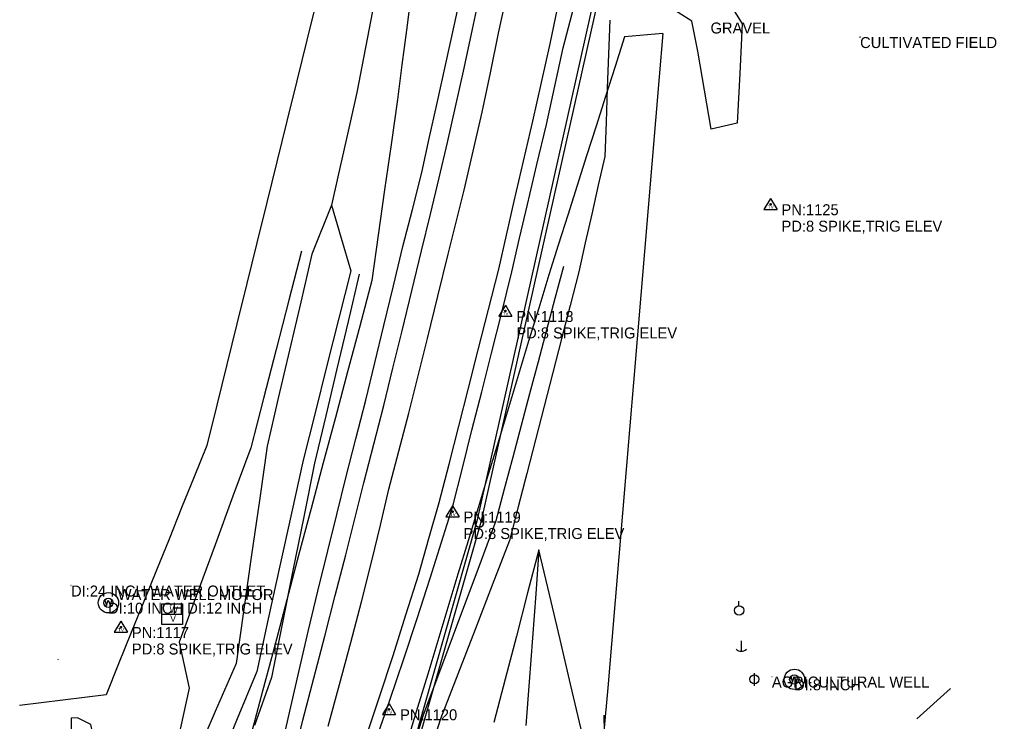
# Model space of a CAD drawing. Extents: x 1445297 to 1476720, y 2042269 to 2057889.
# Drawn here: x 1446111.2 to 1446556, y 2056093.5 to 2056413 of the extents above; entities that cross this region are included whole.
import ezdxf

# ---------------------------------------------------------------- set-up
doc = ezdxf.new("R2010")
doc.units = 0
for name, color, linetype in [('S_DITCHLINE', 7, 'Continuous'), ('S_DRG_PT_SYM', 7, 'Continuous'), ('S_DRIVEWAY', 7, 'Continuous'), ('S_EDGE_PAVEMENT', 7, 'Continuous'), ('S_FIBER_OPTIC_CABLE', 7, 'Continuous'), ('S_MISC_STRUCTURES_ANNOT', 7, 'Continuous'), ('S_MSC_PT_SYM', 7, 'Continuous'), ('S_PAVEMENT_CROWN', 7, 'Continuous'), ('S_SECONDARY_CTL', 7, 'Continuous'), ('S_SECONDARY_CTL_ANNOT', 7, 'Continuous'), ('S_SHOULDER', 7, 'Continuous'), ('S_STREAM', 7, 'Continuous'), ('S_SURVEY_TEXT_ANNOT', 7, 'Continuous'), ('S_TREE', 7, 'Continuous'), ('S_UNDERGROUND_CABLE', 7, 'Continuous'), ('S_UTILITY_POLE', 7, 'Continuous'), ('S_UTL_PT_SYM', 7, 'Continuous'), ('S_WATER_UTILITIES', 7, 'Continuous'), ('S_WATER_WELL', 7, 'Continuous'), ('S_WATER_WELL_ANNOT', 7, 'Continuous')]:
    doc.layers.add(name, color=color, linetype=linetype)

msp = doc.modelspace()

# ---------------------------------------------------------------- linework, layer by layer
at = {"layer": 'S_DITCHLINE'}
for points in [[(1446272.69, 2056420.8), (1446268.75, 2056400.28), (1446264.82, 2056379.76), (1446261.92, 2056366.96), (1446259.02, 2056354.15), (1446256.12, 2056341.35), (1446253.22, 2056328.54), (1446257.65, 2056313.56), (1446262.09, 2056298.58), (1446256.64, 2056277.02), (1446251.19, 2056255.47), (1446245.74, 2056233.92), (1446240.3, 2056212.37), (1446235.02, 2056188.33), (1446229.75, 2056164.29), (1446224.48, 2056140.25), (1446219.21, 2056116.22), (1446210.36, 2056094.7), (1446201.52, 2056073.17)], [(1446379.92, 2056412.73), (1446379.36, 2056397.24), (1446378.81, 2056381.74), (1446378.26, 2056366.24), (1446377.7, 2056350.74), (1446374.74, 2056337.6), (1446371.78, 2056324.46), (1446368.82, 2056311.33), (1446365.85, 2056298.19), (1446361.91, 2056282.89), (1446357.97, 2056267.6), (1446354.03, 2056252.3), (1446350.09, 2056237.01), (1446346.15, 2056221.71), (1446342.21, 2056206.42), (1446338.27, 2056191.12), (1446334.32, 2056175.83), (1446326.48, 2056155.55), (1446318.63, 2056135.28), (1446310.79, 2056115), (1446302.94, 2056094.72), (1446299.07, 2056082.77)], [(1446253.22, 2056328.54), (1446244.33, 2056306.24), (1446239.23, 2056284.37), (1446234.13, 2056262.51), (1446229.02, 2056240.64), (1446223.92, 2056218.78), (1446220.39, 2056194.04), (1446216.86, 2056169.3), (1446213.33, 2056144.57), (1446209.8, 2056119.83), (1446200.32, 2056097.96), (1446190.83, 2056076.09)], [(1446347.72, 2056171.61), (1446342.57, 2056151.95), (1446337.42, 2056132.3), (1446332.26, 2056112.65), (1446327.11, 2056093)], [(1446347.72, 2056171.61), (1446346.24, 2056151.59), (1446344.76, 2056131.58), (1446343.27, 2056111.56), (1446341.79, 2056091.55)], [(1446366.96, 2056089.97), (1446362.15, 2056110.38), (1446357.34, 2056130.79), (1446352.53, 2056151.2), (1446347.72, 2056171.61)], [(1446535.12, 2056108.45), (1446519.81, 2056094.67)]]:
    msp.add_lwpolyline(points, dxfattribs=at)
at = {"layer": 'S_DRG_PT_SYM'}
msp.add_lwpolyline([(1446128.8, 2056121.57), (1446128.8, 2056121.62), (1446128.8, 2056121.57), (1446128.75, 2056121.57), (1446128.8, 2056121.57), (1446128.8, 2056121.52), (1446128.8, 2056121.57), (1446128.85, 2056121.57)], dxfattribs=at)
at = {"layer": 'S_DRIVEWAY'}
msp.add_lwpolyline([(1446406.93, 2056432.04), (1446419.15, 2056428.81), (1446431.37, 2056425.57), (1446440.18, 2056411.01), (1446439.11, 2056388.41), (1446438.04, 2056365.81), (1446426.08, 2056363.05), (1446423.06, 2056380.81), (1446420.03, 2056398.57), (1446417.39, 2056412.23), (1446402.02, 2056422.13)], dxfattribs=at)
at = {"layer": 'S_EDGE_PAVEMENT'}
for points in [[(1446268.92, 2056086.05), (1446275.15, 2056104.73), (1446281.38, 2056123.41), (1446287.17, 2056141.93), (1446292.95, 2056160.46), (1446297.64, 2056176.82), (1446302.34, 2056193.19), (1446306.8, 2056210.53), (1446311.26, 2056227.87), (1446315.64, 2056245.23), (1446320.01, 2056262.58), (1446324.75, 2056281), (1446329.49, 2056299.42), (1446332.95, 2056314.9), (1446336.41, 2056330.37), (1446340.64, 2056348.54), (1446344.87, 2056366.7), (1446348.83, 2056384.34), (1446352.78, 2056401.97), (1446357.85, 2056426.25)], [(1446234.67, 2056072.06), (1446240.25, 2056094), (1446245.2, 2056113.18), (1446250.15, 2056132.36), (1446254.93, 2056150.87), (1446259.71, 2056169.39), (1446263.81, 2056185.72), (1446267.91, 2056202.05), (1446272.48, 2056219.7), (1446277.04, 2056237.34), (1446281.22, 2056254.32), (1446285.4, 2056271.3), (1446289.84, 2056289.55), (1446294.28, 2056307.8), (1446298.3, 2056324.42), (1446302.31, 2056341.03), (1446306, 2056357.13), (1446309.7, 2056373.22), (1446313.6, 2056390.92), (1446317.51, 2056408.61), (1446320.15, 2056421.41)]]:
    msp.add_lwpolyline(points, dxfattribs=at)
at = {"layer": 'S_FIBER_OPTIC_CABLE'}
for p, q in [((1446372.97, 2056423.91), (1446319.44, 2056184.59)), ((1446319.44, 2056184.59), (1446184.54, 2055711.05))]:
    msp.add_line(p, q, dxfattribs=at)
at = {"layer": 'S_MSC_PT_SYM'}
for points in [[(1446425.84, 2056411.69), (1446425.84, 2056411.74), (1446425.84, 2056411.69), (1446425.79, 2056411.69), (1446425.84, 2056411.69), (1446425.84, 2056411.64), (1446425.84, 2056411.69), (1446425.89, 2056411.69)], [(1446493.94, 2056405.06), (1446493.94, 2056405.11), (1446493.94, 2056405.06), (1446493.89, 2056405.06), (1446493.94, 2056405.06), (1446493.94, 2056405.01), (1446493.94, 2056405.06), (1446493.99, 2056405.06)], [(1446134.65, 2056155.34), (1446134.65, 2056155.39), (1446134.65, 2056155.34), (1446134.6, 2056155.34), (1446134.65, 2056155.34), (1446134.65, 2056155.29), (1446134.65, 2056155.34), (1446134.7, 2056155.34)], [(1446155.91, 2056153.73), (1446155.91, 2056153.78), (1446155.91, 2056153.73), (1446155.86, 2056153.73), (1446155.91, 2056153.73), (1446155.91, 2056153.68), (1446155.91, 2056153.73), (1446155.96, 2056153.73)], [(1446453.78, 2056113.9), (1446453.78, 2056113.95), (1446453.78, 2056113.9), (1446453.73, 2056113.9), (1446453.78, 2056113.9), (1446453.78, 2056113.85), (1446453.78, 2056113.9), (1446453.83, 2056113.9)]]:
    msp.add_lwpolyline(points, dxfattribs=at)
at = {"layer": 'S_PAVEMENT_CROWN'}
msp.add_lwpolyline([(1446251.8, 2056091.35), (1446256.96, 2056110.34), (1446262.11, 2056129.33), (1446266.89, 2056147.94), (1446271.67, 2056166.54), (1446275.52, 2056182.85), (1446279.36, 2056199.15), (1446283.88, 2056216.47), (1446288.41, 2056233.78), (1446292.7, 2056250.82), (1446296.99, 2056267.86), (1446301.68, 2056287.03), (1446306.38, 2056306.21), (1446309.99, 2056320.81), (1446313.6, 2056335.41), (1446317.74, 2056353.16), (1446321.87, 2056370.92), (1446325.61, 2056388.84), (1446329.35, 2056406.76), (1446331.97, 2056419.3)], dxfattribs=at)
at = {"layer": 'S_SECONDARY_CTL'}
for p, q in [((1446453.16, 2056331.56), (1446450.15, 2056326.61)), ((1446453.16, 2056331.56), (1446456.11, 2056326.61)), ((1446450.15, 2056326.61), (1446456.11, 2056326.61)), ((1446332.41, 2056282.95), (1446329.4, 2056278)), ((1446332.41, 2056282.95), (1446335.36, 2056278)), ((1446329.4, 2056278), (1446335.36, 2056278)), ((1446308.39, 2056191.62), (1446305.38, 2056186.67)), ((1446308.39, 2056191.62), (1446311.34, 2056186.67)), ((1446305.38, 2056186.67), (1446311.34, 2056186.67)), ((1446157.36, 2056139.05), (1446154.35, 2056134.09)), ((1446157.36, 2056139.05), (1446160.31, 2056134.09)), ((1446154.35, 2056134.09), (1446160.31, 2056134.09)), ((1446279.47, 2056101.61), (1446276.46, 2056096.65)), ((1446279.47, 2056101.61), (1446282.42, 2056096.65)), ((1446276.46, 2056096.65), (1446282.42, 2056096.65))]:
    msp.add_line(p, q, dxfattribs=at)
for centre, radius in [((1446453.16, 2056328.95), 0.311), ((1446453.16, 2056328.95), 0.183), ((1446453.16, 2056328.95), 0.103), ((1446332.41, 2056280.34), 0.311), ((1446332.41, 2056280.34), 0.183), ((1446332.41, 2056280.34), 0.103), ((1446308.39, 2056189.01), 0.311), ((1446308.39, 2056189.01), 0.183), ((1446308.39, 2056189.01), 0.103), ((1446157.36, 2056136.44), 0.311), ((1446157.36, 2056136.44), 0.183), ((1446157.36, 2056136.44), 0.103), ((1446279.47, 2056099), 0.311), ((1446279.47, 2056099), 0.183), ((1446279.47, 2056099), 0.103)]:
    msp.add_circle(centre, radius, dxfattribs=at)
at = {"layer": 'S_SHOULDER'}
for points in [[(1446228.65, 2056073.21), (1446233.59, 2056094.87), (1446238.08, 2056114.61), (1446242.58, 2056134.35), (1446247.08, 2056152.72), (1446251.57, 2056171.09), (1446255.69, 2056187.75), (1446259.81, 2056204.41), (1446264.32, 2056222.07), (1446268.84, 2056239.73), (1446272.99, 2056256.73), (1446277.14, 2056273.74), (1446281.44, 2056291.75), (1446285.75, 2056309.77), (1446290.07, 2056326.55), (1446294.39, 2056343.33), (1446297.79, 2056358.83), (1446301.18, 2056374.34), (1446305.17, 2056392.25), (1446309.16, 2056410.15), (1446311.82, 2056422.86)], [(1446273.3, 2056084.48), (1446279.78, 2056103.22), (1446286.25, 2056121.96), (1446292.24, 2056140.3), (1446298.22, 2056158.65), (1446303.39, 2056175.07), (1446308.56, 2056191.49), (1446312.88, 2056208.79), (1446317.2, 2056226.08), (1446321.67, 2056243.57), (1446326.14, 2056261.07), (1446330.74, 2056279.59), (1446335.33, 2056298.12), (1446338.9, 2056313.5), (1446342.47, 2056328.89), (1446346.78, 2056347.07), (1446351.1, 2056365.26), (1446354.9, 2056382.74), (1446358.7, 2056400.23), (1446364.36, 2056421.63)]]:
    msp.add_lwpolyline(points, dxfattribs=at)
at = {"layer": 'S_STREAM'}
for points in [[(1446239.56, 2056307.57), (1446233.8, 2056285.21), (1446228.05, 2056262.84), (1446222.29, 2056240.48), (1446216.54, 2056218.11), (1446208.39, 2056195.99), (1446200.24, 2056173.86), (1446192.09, 2056151.73), (1446183.94, 2056129.6), (1446188.42, 2056108.64), (1446183.21, 2056085.14), (1446172.21, 2056073.13), (1446152.45, 2056066.59), (1446149.39, 2056066.51), (1446146.53, 2056079.29), (1446143.67, 2056092.08), (1446137.62, 2056095.12), (1446134.69, 2056095.02), (1446134.68, 2056079.99), (1446134.67, 2056064.97), (1446134.81, 2056064.71), (1446127.73, 2056054.02), (1446120.66, 2056043.33)], [(1446358.82, 2056300.54), (1446354.98, 2056286.07), (1446351.14, 2056271.61), (1446347.3, 2056257.14), (1446343.45, 2056242.68), (1446339.61, 2056228.21), (1446335.77, 2056213.75), (1446331.93, 2056199.28), (1446328.09, 2056184.82), (1446319.82, 2056162.68), (1446311.55, 2056140.55), (1446303.28, 2056118.42), (1446295.01, 2056096.28), (1446287.5, 2056072.74)], [(1446265.92, 2056297.1), (1446260.83, 2056275.58), (1446255.74, 2056254.05), (1446250.65, 2056232.53), (1446245.55, 2056211), (1446240.63, 2056186.6), (1446235.71, 2056162.2), (1446230.79, 2056137.8), (1446225.87, 2056113.4), (1446218.18, 2056091.58)], [(1446377.28, 2056096.35), (1446377.45, 2056088.93)]]:
    msp.add_lwpolyline(points, dxfattribs=at)
at = {"layer": 'S_TREE'}
for points in [[(1446289.4, 2056423.98), (1446287.36, 2056408.22), (1446285.31, 2056392.46), (1446283.27, 2056376.69), (1446280.35, 2056356.08), (1446277.44, 2056335.46), (1446274.52, 2056314.84), (1446271.61, 2056294.22), (1446266.08, 2056273.46), (1446260.55, 2056252.69), (1446255.03, 2056231.92), (1446249.5, 2056211.15), (1446243.97, 2056190.39), (1446238.45, 2056169.62), (1446232.92, 2056148.85), (1446227.39, 2056128.08), (1446221.87, 2056107.32), (1446216.34, 2056086.55)], [(1446246.56, 2056422.09), (1446242.01, 2056403.64), (1446237.45, 2056385.18), (1446232.9, 2056366.72), (1446228.35, 2056348.27), (1446223.79, 2056329.81), (1446219.24, 2056311.35), (1446214.69, 2056292.89), (1446210.14, 2056274.44), (1446205.58, 2056255.98), (1446201.03, 2056237.52), (1446196.48, 2056219.07), (1446190.74, 2056204.88), (1446185, 2056190.68), (1446179.26, 2056176.49), (1446173.52, 2056162.3), (1446167.78, 2056148.11), (1446162.05, 2056133.92), (1446156.31, 2056119.73), (1446150.57, 2056105.54), (1446130.88, 2056103.13), (1446111.2, 2056100.73)], [(1446404.15, 2056406.74), (1446386.65, 2056405.15), (1446382.35, 2056391.61), (1446378.04, 2056378.07), (1446373.73, 2056364.54), (1446369.43, 2056351), (1446365.12, 2056337.46), (1446360.82, 2056323.92), (1446356.51, 2056310.38), (1446352.21, 2056296.85), (1446347.61, 2056281.69), (1446343.01, 2056266.54), (1446338.42, 2056251.39), (1446333.82, 2056236.24), (1446329.23, 2056221.08), (1446324.63, 2056205.93), (1446320.03, 2056190.78), (1446315.44, 2056175.63), (1446310.84, 2056160.47), (1446306.25, 2056145.32), (1446301.65, 2056130.17), (1446297.06, 2056115.02), (1446292.46, 2056099.86), (1446287.86, 2056084.71)], [(1446404.15, 2056406.74), (1446402.47, 2056386.88), (1446400.8, 2056367.01), (1446399.12, 2056347.15), (1446397.44, 2056327.29), (1446395.77, 2056307.43), (1446394.09, 2056287.57), (1446392.41, 2056267.7), (1446390.74, 2056247.84), (1446389.06, 2056227.98), (1446387.38, 2056208.12), (1446385.71, 2056188.25), (1446384.03, 2056168.39), (1446382.35, 2056148.53), (1446380.68, 2056128.67), (1446379, 2056108.8), (1446377.32, 2056088.94)]]:
    msp.add_lwpolyline(points, dxfattribs=at)
at = {"layer": 'S_UNDERGROUND_CABLE'}
for p, q in [((1446374.96, 2056423.86), (1446321.29, 2056184.23)), ((1446321.29, 2056184.23), (1446186.26, 2055711.49))]:
    msp.add_line(p, q, dxfattribs=at)
at = {"layer": 'S_UTILITY_POLE'}
for p, q in [((1446438.7, 2056146.15), (1446438.7, 2056148.26)), ((1446439.72, 2056130.11), (1446439.72, 2056125.39)), ((1446445.83, 2056109.71), (1446445.83, 2056115.5))]:
    msp.add_line(p, q, dxfattribs=at)
for centre, radius in [((1446438.82, 2056144.01), 2.13), ((1446445.83, 2056112.64), 2.05)]:
    msp.add_circle(centre, radius, dxfattribs=at)
msp.add_arc((1446439.79, 2056128.81), 3.41, 226.3972, 313.6028, dxfattribs=at)
at = {"layer": 'S_UTL_PT_SYM'}
msp.add_lwpolyline([(1446319.44, 2056184.59), (1446319.44, 2056184.64), (1446319.44, 2056184.59), (1446319.39, 2056184.59), (1446319.44, 2056184.59), (1446319.44, 2056184.54), (1446319.44, 2056184.59), (1446319.49, 2056184.59)], dxfattribs=at)
at = {"layer": 'S_WATER_UTILITIES'}
for p, q in [((1446175.98, 2056147.06), (1446185.4, 2056147.06)), ((1446175.98, 2056137.64), (1446175.98, 2056147.06)), ((1446185.4, 2056147.06), (1446185.4, 2056137.64)), ((1446175.98, 2056142.37), (1446185.4, 2056142.37)), ((1446185.4, 2056137.64), (1446175.98, 2056137.64))]:
    msp.add_line(p, q, dxfattribs=at)
at = {"layer": 'S_WATER_WELL'}
for p, q in [((1446150.1, 2056148.75), (1446150.76, 2056146.27)), ((1446150.76, 2056146.27), (1446151.58, 2056148.75)), ((1446151.58, 2056148.75), (1446152.62, 2056146.27)), ((1446152.62, 2056146.27), (1446153.2, 2056148.79)), ((1446462.47, 2056113.88), (1446463.12, 2056111.4)), ((1446463.12, 2056111.4), (1446463.94, 2056113.88)), ((1446463.94, 2056113.88), (1446464.98, 2056111.4)), ((1446464.98, 2056111.4), (1446465.57, 2056113.92))]:
    msp.add_line(p, q, dxfattribs=at)
for centre, radius in [((1446151.67, 2056147.49), 4.63), ((1446151.64, 2056147.49), 2.13), ((1446464.03, 2056112.62), 4.63), ((1446464, 2056112.62), 2.13)]:
    msp.add_circle(centre, radius, dxfattribs=at)

# ---------------------------------------------------------------- texts
at = {"layer": 'S_MISC_STRUCTURES_ANNOT'}
for s, p in [('DI:24 INCH WATER OUTLET', (1446134.65, 2056150.34)), ('WATER WELL MOTOR', (1446155.91, 2056148.73)), ('AGRICULTURAL WELL', (1446453.78, 2056108.9))]:
    msp.add_text(s, height=5, dxfattribs=at).set_placement(p)
at = {"layer": 'S_SECONDARY_CTL'}
for p in [(1446451.96, 2056326.94), (1446331.21, 2056278.33), (1446307.18, 2056187), (1446156.15, 2056134.43), (1446278.27, 2056096.99)]:
    msp.add_text('TV', height=1.5, dxfattribs=at).set_placement(p)
at = {"layer": 'S_SECONDARY_CTL_ANNOT'}
for s, p in [('PN:1125', (1446458.16, 2056323.95)), ('PD:8 SPIKE,TRIG ELEV', (1446458.16, 2056316.45)), ('PN:1118', (1446337.41, 2056275.34)), ('PD:8 SPIKE,TRIG ELEV', (1446337.41, 2056267.84)), ('PN:1119', (1446313.39, 2056184.01)), ('PD:8 SPIKE,TRIG ELEV', (1446313.39, 2056176.51)), ('PN:1117', (1446162.36, 2056131.44)), ('PD:8 SPIKE,TRIG ELEV', (1446162.36, 2056123.94)), ('PN:1120', (1446284.47, 2056094))]:
    msp.add_text(s, height=5, dxfattribs=at).set_placement(p)
at = {"layer": 'S_SURVEY_TEXT_ANNOT'}
for s, p in [('GRAVEL', (1446425.84, 2056406.69)), ('CULTIVATED FIELD', (1446493.94, 2056400.06))]:
    msp.add_text(s, height=5, dxfattribs=at).set_placement(p)
at = {"layer": 'S_UTL_PT_SYM'}
msp.add_text('U', height=6, dxfattribs=at).set_placement((1446317.66, 2056181.69))
at = {"layer": 'S_WATER_UTILITIES'}
for s, p in [('W', (1446179.53, 2056142.9)), ('V', (1446179.77, 2056138.84))]:
    msp.add_text(s, height=3, dxfattribs=at).set_placement(p)
at = {"layer": 'S_WATER_WELL_ANNOT'}
for s, p in [('DI:10 INCH DI:12 INCH', (1446151.52, 2056142.52)), ('DI:8 INCH', (1446463.88, 2056107.65))]:
    msp.add_text(s, height=5, dxfattribs=at).set_placement(p)

doc.saveas('drawing.dxf')
